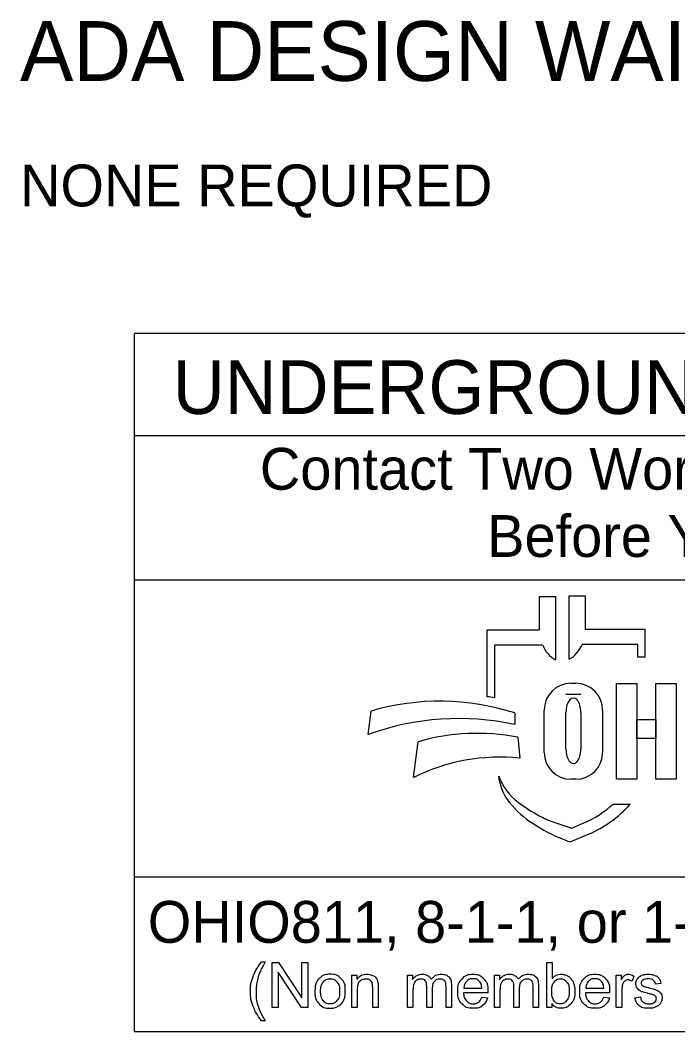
# Model space of a CAD drawing. Extents: x -11.1 to 43.5, y 0 to 22.
# Drawn here: x 1.995 to 4.196, y 2.143 to 5.529 of the extents above; entities that cross this region are included whole.
import ezdxf

# ---------------------------------------------------------------- set-up
doc = ezdxf.new("R2010")
doc.units = 0
doc.layers.add('SH_Data', color=7, linetype='Continuous')
doc.layers.add('SH_Text', color=7, linetype='Continuous')

msp = doc.modelspace()

# ---------------------------------------------------------------- linework, layer by layer
at = {"layer": 'SH_Data'}
for p, q in [((2.3775, 2.1428), (2.3775, 4.4803)), ((6.6275, 4.4803), (2.3775, 4.4803)), ((2.3775, 4.1387), (6.6275, 4.1387)), ((2.3775, 3.6553), (6.6275, 3.6553)), ((6.6275, 2.6607), (2.3775, 2.6607)), ((6.6275, 2.1428), (2.3775, 2.1428))]:
    msp.add_line(p, q, dxfattribs=at)
at = {"layer": 'SH_Text'}
for p, q in [((3.7335, 3.4883), (3.7335, 3.5998)), ((3.7335, 3.5998), (3.7872, 3.5998)), ((3.7872, 3.5998), (3.7872, 3.3877)), ((3.8329, 3.39), (3.8329, 3.6021)), ((3.8329, 3.6021), (3.8865, 3.6021)), ((3.8865, 3.6021), (3.8865, 3.4906)), ((3.5576, 3.2644), (3.5576, 3.4883)), ((3.5576, 3.4883), (3.7335, 3.4883)), ((3.8865, 3.4906), (4.0857, 3.4906)), ((4.0857, 3.4906), (4.0857, 3.3968)), ((3.5828, 3.4369), (3.5828, 3.26)), ((3.7439, 3.4369), (3.5828, 3.4369)), ((4.0625, 3.4392), (3.8761, 3.4392)), ((4.0625, 3.3968), (4.0625, 3.4392)), ((4.0857, 3.3968), (4.0625, 3.3968)), ((3.8385, 3.3091), (3.8551, 3.3091)), ((3.8718, 3.2721), (3.822, 3.2721)), ((3.7491, 3.0776), (3.7491, 3.2196)), ((3.9445, 3.2196), (3.9445, 3.0776)), ((3.1602, 3.1381), (3.1696, 3.2162)), ((3.6509, 3.2097), (3.6509, 3.1709)), ((3.822, 3.089), (3.822, 3.2114)), ((3.8718, 3.2114), (3.8718, 3.089)), ((3.6608, 3.1291), (3.6671, 3.0582)), ((3.312, 2.9936), (3.3267, 3.1137)), ((3.5997, 2.9807), (3.5967, 2.9986)), ((3.8551, 2.9882), (3.8385, 2.9882)), ((3.98, 2.9048), (4.0375, 2.9048)), ((3.7816, 2.8444), (3.841, 2.8239)), ((3.841, 2.8239), (3.8821, 2.8417)), ((3.835, 2.7769), (3.7976, 2.7934)), ((3.8983, 2.8044), (3.835, 2.7769))]:
    msp.add_line(p, q, dxfattribs=at)
for points in [[(3.991, 3.3081), (4.0589, 3.3081), (4.0589, 2.9881), (3.991, 2.9881)], [(4.1231, 3.3081), (4.1911, 3.3081), (4.1911, 2.9881), (4.1231, 2.9881)], [(4.0589, 3.1882), (4.1231, 3.1882), (4.1231, 3.1242), (4.0589, 3.1242)]]:
    msp.add_lwpolyline(points, close=True, dxfattribs=at)
for points in [[(2.8021, 2.3766), (2.8153, 2.3766)], [(2.8389, 2.2239), (2.8389, 2.3741), (2.8592, 2.3741), (2.9382, 2.2561), (2.9382, 2.3741), (2.9572, 2.3741), (2.9572, 2.2239), (2.9369, 2.2239), (2.8579, 2.3419), (2.8579, 2.2239), (2.8389, 2.2239)], [(3.7743, 2.2239), (3.7573, 2.2239), (3.7573, 2.3741), (3.7757, 2.3741), (3.7757, 2.3206)], [(3.1048, 2.2239), (3.1048, 2.3328), (3.1214, 2.3328), (3.1214, 2.3173)], [(3.2912, 2.2239), (3.2912, 2.3328), (3.3077, 2.3328), (3.3077, 2.3174)], [(3.5826, 2.2239), (3.5826, 2.3328), (3.5991, 2.3328), (3.5991, 2.3174)], [(3.9904, 2.2239), (3.9904, 2.3328), (4.007, 2.3328), (4.007, 2.3163)], [(4.0495, 2.3293), (4.043, 2.3122)], [(4.1394, 2.3046), (4.1213, 2.3022)], [(3.1233, 2.2833), (3.1233, 2.2239), (3.1048, 2.2239)], [(3.1932, 2.2908), (3.1932, 2.2239), (3.1748, 2.2239), (3.1748, 2.2901)], [(3.3097, 2.2803), (3.3097, 2.2239), (3.2912, 2.2239)], [(3.3743, 2.2871), (3.3743, 2.2239), (3.3559, 2.2239), (3.3559, 2.2946)], [(3.4388, 2.2986), (3.4388, 2.2239), (3.4203, 2.2239), (3.4203, 2.2924)], [(3.56, 2.2736), (3.4788, 2.2736)], [(3.4799, 2.2887), (3.5406, 2.2887)], [(3.601, 2.2803), (3.601, 2.2239), (3.5826, 2.2239)], [(3.6657, 2.2871), (3.6657, 2.2239), (3.6473, 2.2239), (3.6473, 2.2946)], [(3.7301, 2.2986), (3.7301, 2.2239), (3.7117, 2.2239), (3.7117, 2.2924)], [(3.968, 2.2736), (3.8868, 2.2736)], [(3.8879, 2.2887), (3.9486, 2.2887)], [(4.0088, 2.2809), (4.0088, 2.2239), (3.9904, 2.2239)], [(3.5404, 2.2591), (3.5595, 2.2567)], [(3.7743, 2.2375), (3.7743, 2.2239)], [(3.9484, 2.2591), (3.9675, 2.2567)], [(4.053, 2.2564), (4.0712, 2.2593)], [(2.8153, 2.1798), (2.8021, 2.1798)]]:
    msp.add_lwpolyline(points, dxfattribs=at)
for centre, radius, start, end in [((3.8353, 3.4736), 0.0985, 201.9296, 240.7469), ((3.7847, 3.476), 0.0985, 299.2531, 338.0704), ((3.8385, 3.2196), 0.0895, 90, 180), ((3.8551, 3.2196), 0.0895, 0, 90), ((3.4295, 2.4554), 0.8191, 79.2074, 81.0007), ((3.3997, 2.4302), 0.8191, 72.1402, 106.3144), ((3.4628, 2.2991), 0.8919, 77.8238, 109.8274), ((3.5267, 2.4094), 0.7322, 79.44, 105.8467), ((3.5987, 2.4262), 0.6357, 83.8248, 116.8021), ((3.8385, 3.0776), 0.0895, 180, 270), ((3.8551, 3.0776), 0.0895, 270, 0), ((3.7841, 3.0707), 0.2008, 201.0457, 232.5314), ((3.741, 3.0048), 0.1433, 189.6817, 216.0884), ((3.8747, 3.1022), 0.3088, 216.0884, 235.7167), ((3.9766, 3.3219), 0.5173, 232.5314, 241.794), ((3.7387, 3.1722), 0.3602, 293.4582, 312.0712), ((3.7387, 3.1722), 0.401, 293.4582, 317.8286), ((4.0412, 3.3465), 0.6044, 235.7167, 246.2325), ((3.8914, 3.1631), 0.3371, 241.794, 250.9821)]:
    msp.add_arc(centre, radius, start, end, dxfattribs=at)
for centre, start_param, end_param in [((3.8469, 3.2114), 4.712389, 7.853982), ((3.8469, 3.089), 1.570796, 4.712389)]:
    msp.add_ellipse(centre, major_axis=(0, 0.0484), ratio=0.514403, start_param=start_param, end_param=end_param, dxfattribs=at)
for points in [[(2.8021, 2.1798), (2.7869, 2.199), (2.7763, 2.2248), (2.7657, 2.2506), (2.7657, 2.2783), (2.7657, 2.3026), (2.7736, 2.325), (2.7829, 2.3509), (2.8021, 2.3766)], [(2.8153, 2.3766), (2.8029, 2.3553), (2.7989, 2.3462), (2.7927, 2.332), (2.7891, 2.3167), (2.7847, 2.2975), (2.7847, 2.2782), (2.7847, 2.2289), (2.8153, 2.1798)], [(2.9814, 2.2783), (2.9814, 2.3085), (2.9981, 2.3231), (3.0122, 2.3352), (3.0323, 2.3352), (3.0547, 2.3352), (3.069, 2.3205), (3.0832, 2.3058), (3.0832, 2.2799), (3.0832, 2.2589), (3.0769, 2.2469), (3.0706, 2.2348), (3.0586, 2.2282), (3.0466, 2.2215), (3.0323, 2.2215), (3.0095, 2.2215), (2.9954, 2.2362), (2.9814, 2.2508), (2.9814, 2.2783)], [(3.0003, 2.2783), (3.0003, 2.2574), (3.0094, 2.247), (3.0185, 2.2366), (3.0323, 2.2366), (3.046, 2.2366), (3.0551, 2.2471), (3.0642, 2.2575), (3.0642, 2.279), (3.0642, 2.2991), (3.0551, 2.3095), (3.0459, 2.3199), (3.0323, 2.3199), (3.0185, 2.3199), (3.0094, 2.3096), (3.0003, 2.2992), (3.0003, 2.2783)], [(3.1214, 2.3173), (3.1334, 2.3352), (3.156, 2.3352), (3.1659, 2.3352), (3.1741, 2.3316), (3.1823, 2.3281), (3.1864, 2.3224), (3.1905, 2.3166), (3.1922, 2.3087), (3.1932, 2.3036), (3.1932, 2.2908)], [(3.1748, 2.2901), (3.1748, 2.3013), (3.1726, 2.3069), (3.1705, 2.3125), (3.165, 2.3158), (3.1595, 2.3191), (3.1521, 2.3191), (3.1404, 2.3191), (3.1318, 2.3117), (3.1233, 2.3042), (3.1233, 2.2833)], [(3.3077, 2.3174), (3.3128, 2.3254), (3.3214, 2.3303), (3.3299, 2.3352), (3.3407, 2.3352), (3.3528, 2.3352), (3.3606, 2.3301), (3.3683, 2.3251), (3.3715, 2.3161), (3.3844, 2.3352), (3.4051, 2.3352), (3.4213, 2.3352), (3.43, 2.3262), (3.4388, 2.3172), (3.4388, 2.2986)], [(3.3559, 2.2946), (3.3559, 2.3069), (3.3514, 2.313), (3.3469, 2.3191), (3.3366, 2.3191), (3.3288, 2.3191), (3.3222, 2.315), (3.3156, 2.311), (3.3126, 2.3031), (3.3097, 2.2952), (3.3097, 2.2803)], [(3.4203, 2.2924), (3.4203, 2.3035), (3.4185, 2.3083), (3.4168, 2.3132), (3.412, 2.3162), (3.4073, 2.3191), (3.401, 2.3191), (3.3895, 2.3191), (3.3819, 2.3115), (3.3743, 2.3039), (3.3743, 2.2871)], [(3.5595, 2.2567), (3.555, 2.24), (3.5428, 2.2307), (3.5306, 2.2215), (3.5117, 2.2215), (3.4878, 2.2215), (3.4738, 2.2362), (3.4598, 2.2509), (3.4598, 2.2774), (3.4598, 2.3049), (3.474, 2.32), (3.4881, 2.3352), (3.5106, 2.3352), (3.5324, 2.3352), (3.5463, 2.3203), (3.5601, 2.3055), (3.5601, 2.2785), (3.5601, 2.2769), (3.56, 2.2736)], [(3.5406, 2.2887), (3.5394, 2.3025), (3.5337, 2.3094), (3.5249, 2.3201), (3.5108, 2.3201), (3.4981, 2.3201), (3.4894, 2.3115), (3.4808, 2.303), (3.4799, 2.2887)], [(3.5991, 2.3174), (3.6042, 2.3254), (3.6127, 2.3303), (3.6212, 2.3352), (3.6321, 2.3352), (3.6442, 2.3352), (3.6519, 2.3301), (3.6597, 2.3251), (3.6628, 2.3161), (3.6758, 2.3352), (3.6965, 2.3352), (3.7127, 2.3352), (3.7214, 2.3262), (3.7301, 2.3172), (3.7301, 2.2986)], [(3.6473, 2.2946), (3.6473, 2.3069), (3.6428, 2.313), (3.6383, 2.3191), (3.628, 2.3191), (3.6202, 2.3191), (3.6136, 2.315), (3.607, 2.311), (3.604, 2.3031), (3.601, 2.2952), (3.601, 2.2803)], [(3.7117, 2.2924), (3.7117, 2.3035), (3.7099, 2.3083), (3.7081, 2.3132), (3.7034, 2.3162), (3.6987, 2.3191), (3.6923, 2.3191), (3.6809, 2.3191), (3.6733, 2.3115), (3.6657, 2.3039), (3.6657, 2.2871)], [(3.7741, 2.2792), (3.7741, 2.2596), (3.7794, 2.2509), (3.7881, 2.2366), (3.8029, 2.2366), (3.815, 2.2366), (3.8238, 2.2471), (3.8326, 2.2576), (3.8326, 2.2784), (3.8326, 2.2998), (3.8241, 2.3099), (3.8157, 2.3201), (3.8038, 2.3201), (3.7917, 2.3201), (3.7829, 2.3096), (3.7741, 2.299), (3.7741, 2.2792)], [(3.7757, 2.3206), (3.7874, 2.3352), (3.8055, 2.3352), (3.8155, 2.3352), (3.8245, 2.3311), (3.8335, 2.3271), (3.8392, 2.3198), (3.845, 2.3124), (3.8483, 2.3021), (3.8516, 2.2918), (3.8516, 2.28), (3.8516, 2.252), (3.8378, 2.2368), (3.8239, 2.2215), (3.8046, 2.2215), (3.7853, 2.2215), (3.7743, 2.2375)], [(3.9675, 2.2567), (3.963, 2.24), (3.9508, 2.2307), (3.9386, 2.2215), (3.9196, 2.2215), (3.8958, 2.2215), (3.8818, 2.2362), (3.8678, 2.2509), (3.8678, 2.2774), (3.8678, 2.3049), (3.882, 2.32), (3.8961, 2.3352), (3.9186, 2.3352), (3.9404, 2.3352), (3.9543, 2.3203), (3.9681, 2.3055), (3.9681, 2.2785), (3.9681, 2.2769), (3.968, 2.2736)], [(3.9486, 2.2887), (3.9474, 2.3025), (3.9417, 2.3094), (3.9328, 2.3201), (3.9188, 2.3201), (3.9061, 2.3201), (3.8974, 2.3115), (3.8888, 2.303), (3.8879, 2.2887)], [(4.007, 2.3163), (4.0133, 2.3278), (4.0187, 2.3315), (4.0241, 2.3352), (4.0305, 2.3352), (4.0398, 2.3352), (4.0495, 2.3293)], [(4.043, 2.3122), (4.0363, 2.3162), (4.0295, 2.3162), (4.0235, 2.3162), (4.0187, 2.3125), (4.0139, 2.3089), (4.0119, 2.3024), (4.0088, 2.2926), (4.0088, 2.2809)], [(4.1213, 2.3022), (4.1201, 2.3106), (4.1142, 2.3153), (4.1083, 2.3201), (4.0975, 2.3201), (4.0848, 2.3201), (4.0794, 2.3159), (4.0739, 2.3116), (4.0739, 2.306), (4.0739, 2.3024), (4.0762, 2.2995), (4.0785, 2.2966), (4.0833, 2.2946), (4.086, 2.2936), (4.0996, 2.2899), (4.1192, 2.2847), (4.1269, 2.2813), (4.1347, 2.278), (4.1391, 2.2717), (4.1435, 2.2653), (4.1435, 2.2559), (4.1435, 2.2467), (4.1381, 2.2386), (4.1327, 2.2304), (4.1226, 2.226), (4.1124, 2.2215), (4.0996, 2.2215), (4.0784, 2.2215), (4.0672, 2.2303), (4.0561, 2.2391), (4.053, 2.2564)], [(4.0712, 2.2593), (4.0727, 2.2483), (4.0798, 2.2425), (4.0868, 2.2366), (4.0995, 2.2366), (4.1122, 2.2366), (4.1184, 2.2418), (4.1245, 2.247), (4.1245, 2.254), (4.1245, 2.2602), (4.1191, 2.2638), (4.1153, 2.2663), (4.1002, 2.2701), (4.0799, 2.2752), (4.072, 2.2789), (4.0642, 2.2827), (4.0601, 2.2893), (4.0561, 2.2959), (4.0561, 2.3038), (4.0561, 2.3111), (4.0594, 2.3173), (4.0628, 2.3235), (4.0685, 2.3276), (4.0728, 2.3308), (4.0803, 2.333), (4.0877, 2.3352), (4.0962, 2.3352), (4.109, 2.3352), (4.1187, 2.3315), (4.1284, 2.3278), (4.133, 2.3215), (4.1377, 2.3152), (4.1394, 2.3046)], [(3.4788, 2.2736), (3.4799, 2.2557), (3.489, 2.2462), (3.4981, 2.2366), (3.5117, 2.2366), (3.5219, 2.2366), (3.5291, 2.242), (3.5362, 2.2473), (3.5404, 2.2591)], [(3.8868, 2.2736), (3.8879, 2.2557), (3.897, 2.2462), (3.9061, 2.2366), (3.9197, 2.2366), (3.9299, 2.2366), (3.937, 2.242), (3.9442, 2.2473), (3.9484, 2.2591)]]:
    msp.add_open_spline(points, degree=3, dxfattribs=at)

# ---------------------------------------------------------------- texts
for s, height, p in [('ADA DESIGN WAIVERS', 0.2, (1.9944, 5.3256)), ('NONE REQUIRED', 0.14, (1.9944, 4.9056)), ('UNDERGROUND UTILITIES', 0.18, (2.5057, 4.2106)), ('Contact Two Working Days', 0.14, (2.7972, 3.9571)), ('Before You Dig', 0.14, (3.5583, 3.7321)), ('OHIO811, 8-1-1, or 1-800-362-2764', 0.14, (2.422, 2.4406))]:
    msp.add_text(s, height=height, dxfattribs=at).set_placement(p)

doc.saveas('drawing.dxf')
